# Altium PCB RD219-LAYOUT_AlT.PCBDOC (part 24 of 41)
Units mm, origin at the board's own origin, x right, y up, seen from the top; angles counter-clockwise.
Board outline 209.75 x 159.97 mm, 2 copper layers (TOP, BOTTOM), stack 0 mm thick; 398 components, 199 nets, 1469 pads, 0 vias.
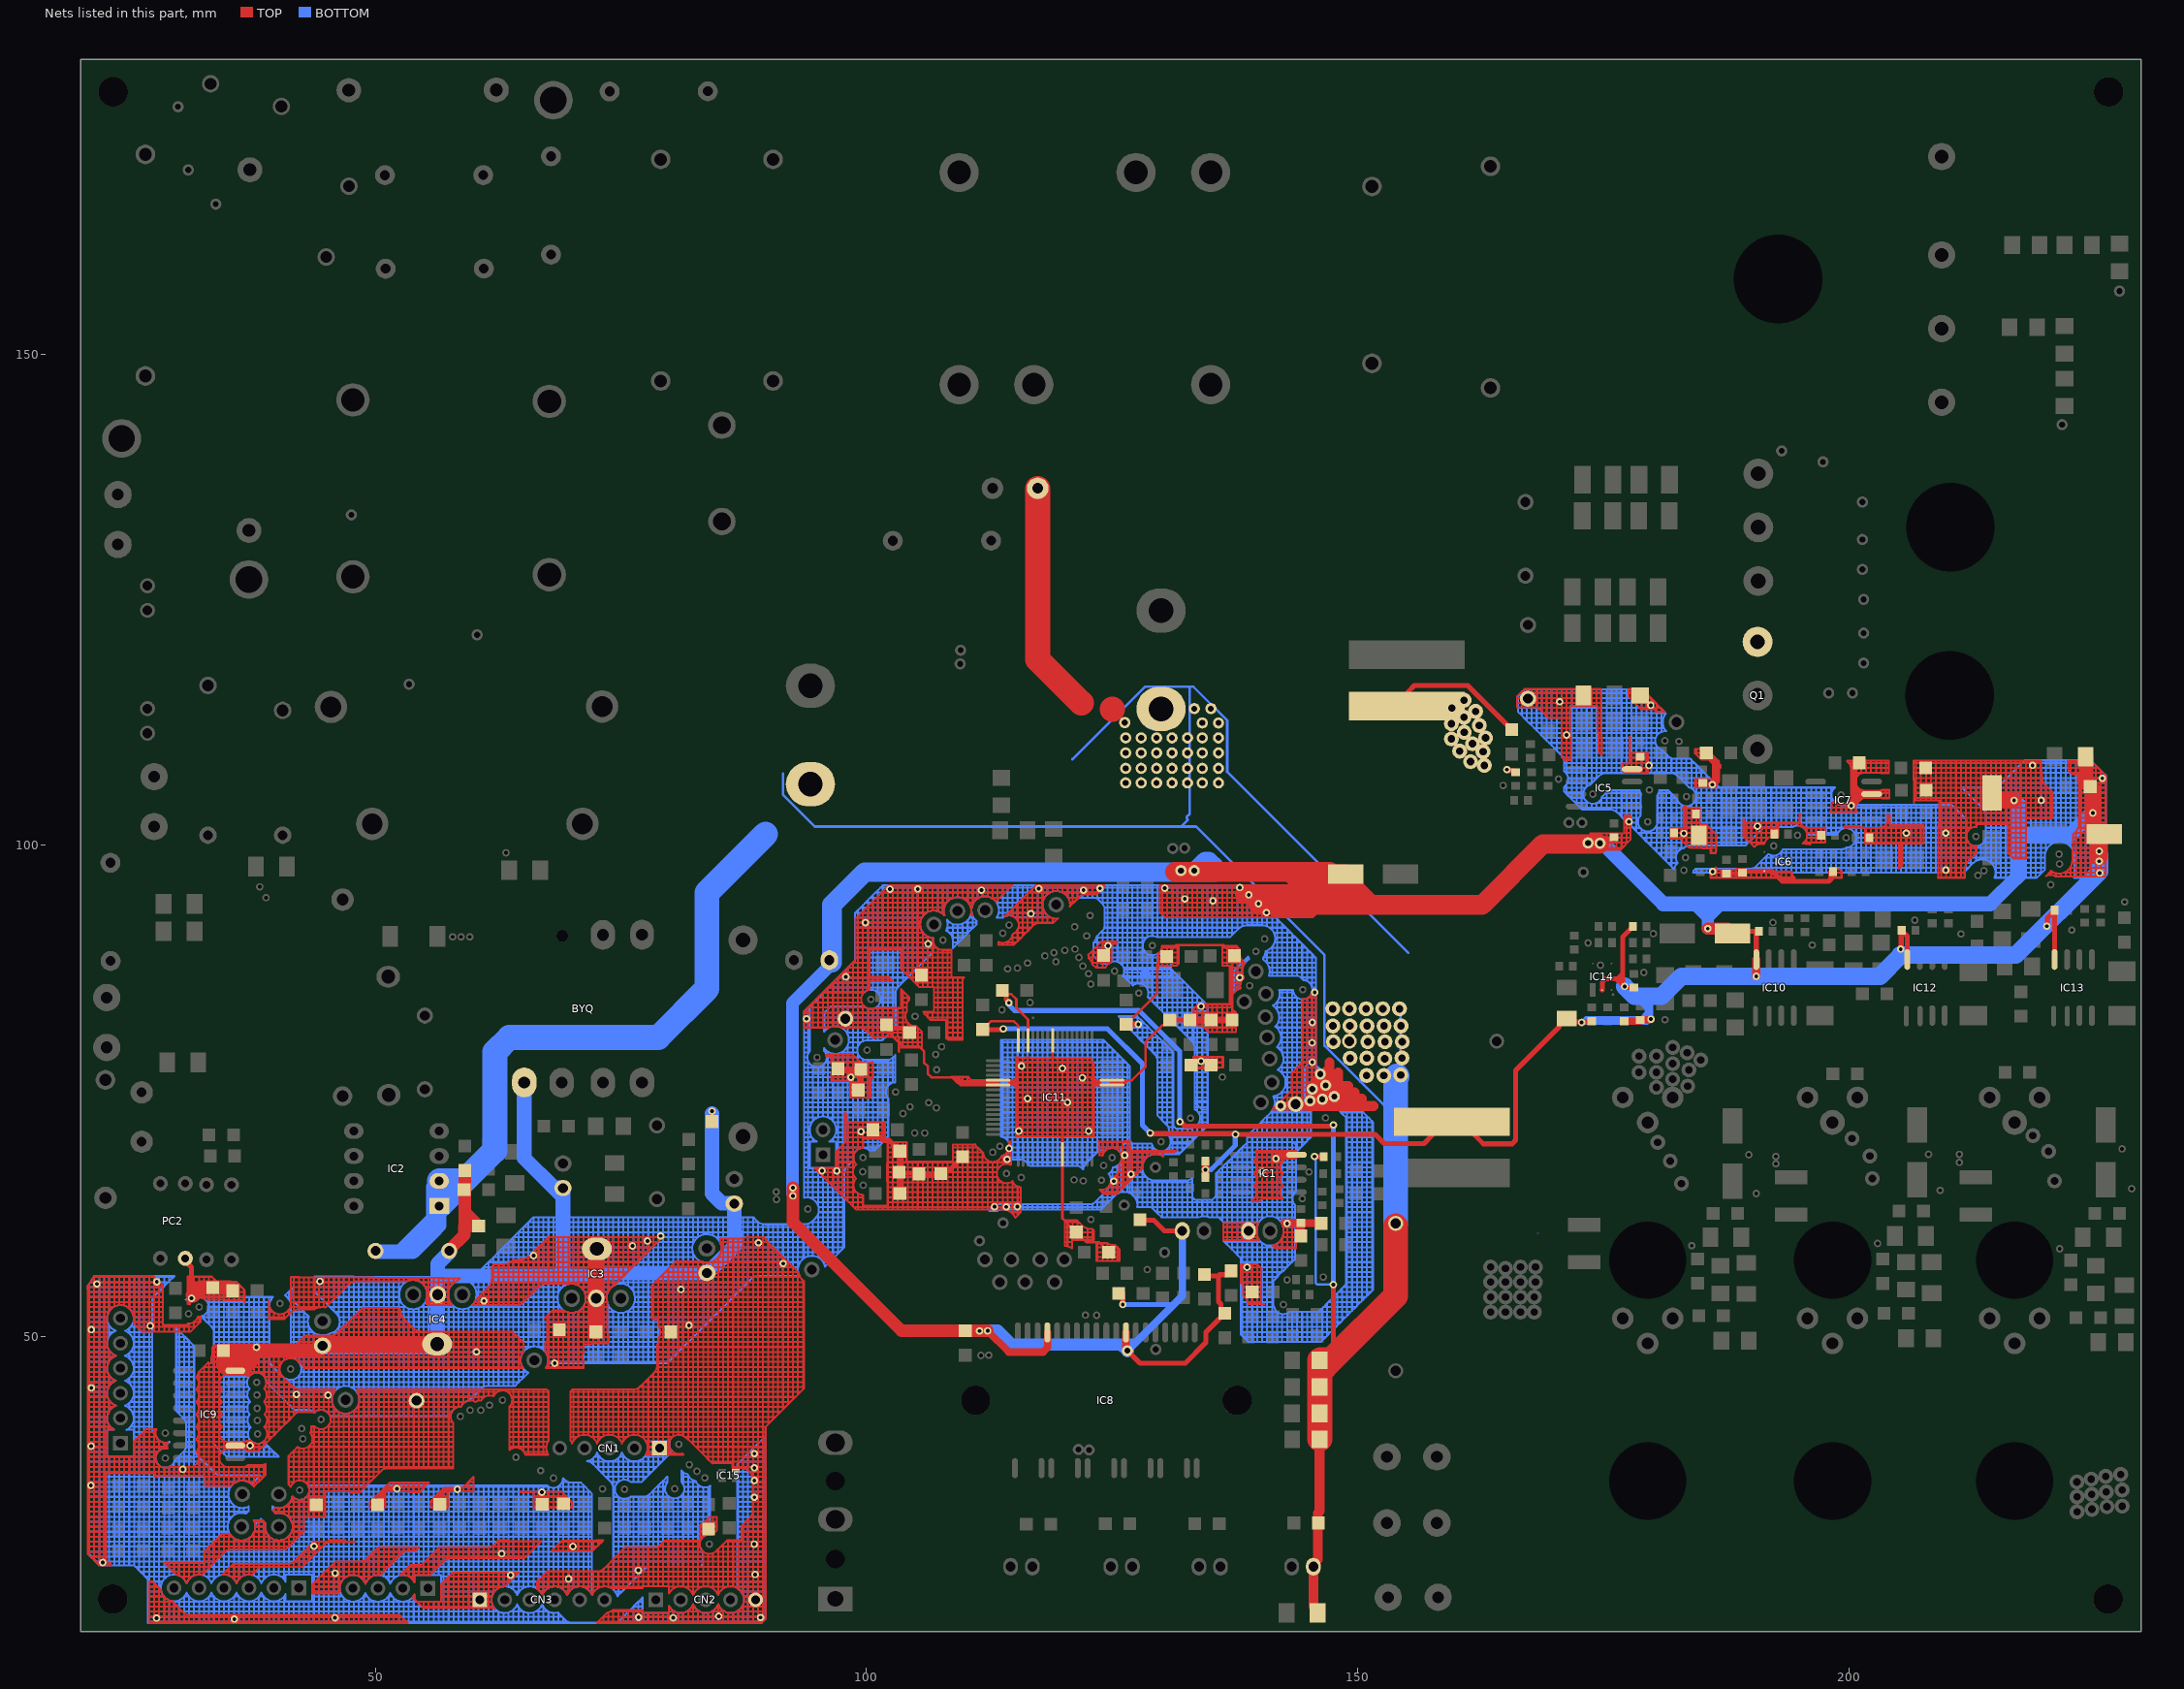
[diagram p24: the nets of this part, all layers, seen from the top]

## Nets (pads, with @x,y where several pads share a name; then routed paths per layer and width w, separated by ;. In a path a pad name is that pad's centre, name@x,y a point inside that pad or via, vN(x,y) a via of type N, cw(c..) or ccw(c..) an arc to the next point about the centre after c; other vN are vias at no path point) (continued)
GND: (continued)
  BOTTOM w0.203: 51.877,27.62 51.877,28.128 ; 51.877,27.62 52.385,27.62 ; 51.877,28.128 51.877,28.636 ; 51.877,28.128 52.385,28.128 ; 51.877,28.636 51.877,29.144 ; 51.877,28.636 52.385,28.636 ; 51.877,29.144 51.877,29.652 ; 51.877,29.144 52.385,29.144 ; 51.877,29.652 51.877,30.16 ; 51.877,29.652 52.385,29.652 ; 51.877,30.16 51.877,30.668 ; 51.877,30.16 52.385,30.16 ; 51.877,30.668 51.877,31.176 ; 51.877,30.668 52.385,30.668 ; 51.877,31.176 51.877,31.684 ; 51.877,31.176 52.385,31.176 ; 51.877,31.684 51.877,32.192 ; 51.877,31.684 52.385,31.684 ; 51.877,32.192 51.877,32.7 ; 51.877,32.192 52.385,32.192 ; 51.877,32.7 51.877,33.208 ; 51.877,32.7 52.385,32.7 ; 51.877,33.208 51.877,33.716 ; 51.877,33.208 52.385,33.208 ; 51.877,33.716 51.877,34.224 ; 51.877,33.716 52.385,33.716 ; 51.877,34.224 51.877,34.732 ; 51.877,34.224 pad.@52.385,34.224 ; 51.877,34.732 51.877,34.866 ; 51.877,34.732 pad.@52.385,34.732 ; 51.877,34.866 pad.@52.385,34.866 ; 51.877,41.938 51.877,42.352 ; 51.877,41.938 52.385,41.938 ; 51.877,42.352 51.877,42.86 ; 51.877,42.352 52.385,42.352 ; 51.877,42.86 51.877,43.368 ; 51.877,42.86 52.385,42.86 ; 51.877,43.368 51.877,43.876 ; 51.877,43.368 52.385,43.368 ; 51.877,43.876 51.877,44.384 ; 51.877,43.876 52.385,43.876 ; 51.877,44.384 51.877,44.892 ; 51.877,44.384 52.385,44.384 ; 51.877,44.892 51.877,45.4 ; 51.877,44.892 52.385,44.892 ; 51.877,45.4 51.877,45.908 ; 51.877,45.4 52.385,45.4 ; 51.877,45.908 51.877,46.416 ; 51.877,45.908 52.385,45.908 ; 51.877,46.416 51.877,46.924 ; 51.877,46.416 52.385,46.416 ; 51.877,46.924 51.877,47.432 ; 51.877,46.924 52.385,46.924 ; 51.877,47.432 51.877,47.94 ; 51.877,47.432 52.385,47.432 ; 51.877,47.94 51.877,48.448 ; 51.877,47.94 52.385,47.94 ; 51.877,48.448 51.877,48.956 ; 51.877,48.448 52.385,48.448 ; 51.877,48.956 51.877,49.464 ; 51.877,48.956 52.385,48.956 ; 51.877,49.464 51.877,49.972 ; 51.877,49.464 52.385,49.464 ; 51.877,49.972 51.877,50.48 ; 51.877,49.972 52.385,49.972 ; 51.877,50.48 51.877,50.988 ; 51.877,50.48 52.385,50.48 ; 51.877,50.988 51.877,51.496 ; 51.877,50.988 52.385,50.988 ; 51.877,51.496 51.877,52.004 ; 51.877,51.496 52.385,51.496 ; 51.877,52.004 51.877,52.512 ; 51.877,52.004 52.385,52.004 ; 51.877,52.512 51.877,53.02 ; 51.877,52.512 52.385,52.512 ; 51.877,53.02 51.877,53.528 ; 51.877,53.02 52.385,53.02 ; 51.877,53.528 51.877,54.036 ; 51.877,53.528 52.385,53.528 ; 51.877,54.036 52.385,54.036 ; 51.877,54.036 51.877,54.544 ; 51.877,54.544 51.877,55.052 ; 51.877,54.544 52.385,54.544 ; 51.877,55.052 51.877,55.56 ; 51.877,55.052 52.385,55.052 ; 51.877,55.56 51.877,56.068 ; 51.877,55.56 52.385,55.56 ; 51.877,56.068 51.877,56.095 ; 51.877,56.068 52.385,56.068 ; 51.877,56.095 52.385,56.093 ; 52.17,25.588 cw(c52.809,24.397) 52.174,25.59 cw(c52.809,24.397) 52.385,25.68 ; 52.385,20.889 52.385,21.016 ; 52.385,20.889 52.893,20.889 ; 52.385,21.016 52.385,21.524 ; 52.385,21.016 52.893,21.016 ; 52.385,21.524 52.385,22.032 ; 52.385,21.524 52.893,21.524 ; 52.385,22.032 52.385,22.54 ; 52.385,22.032 52.893,22.032 ; 52.385,22.54 52.385,23.048 ; 52.385,22.54 52.893,22.54 ; 52.385,23.048 52.725,23.048 ; 52.385,25.68 cw(c52.809,24.397) 52.391,25.682 cw(c52.809,24.397) 52.893,25.746 ; 52.385,25.68 52.385,26.096 ; 52.385,26.096 52.385,26.604 ; 52.385,26.096 52.893,26.096 ; 52.385,26.604 52.385,27.112 ; 52.385,26.604 52.893,26.604 ; 52.385,27.112 52.385,27.62 ; 52.385,27.112 52.893,27.112 ; 52.385,27.62 52.385,28.128 ; 52.385,27.62 52.893,27.62 ; 52.385,28.128 52.385,28.636 ; 52.385,28.128 52.893,28.128 ; 52.385,28.636 52.385,29.144 ; 52.385,28.636 52.893,28.636 ; 52.385,29.144 52.385,29.652 ; 52.385,29.144 52.893,29.144 ; 52.385,29.652 52.385,30.16 ; 52.385,29.652 52.893,29.652 ; 52.385,30.16 52.385,30.668 ; 52.385,30.16 52.893,30.16 ; 52.385,30.668 52.385,31.176 ; 52.385,30.668 52.893,30.668 ; 52.385,31.176 52.385,31.684 ; 52.385,31.176 52.893,31.176 ; 52.385,31.684 52.385,32.192 ; 52.385,31.684 52.893,31.684 ; 52.385,32.192 52.385,32.7 ; 52.385,32.192 52.893,32.192 ; 52.385,32.7 52.385,33.208 ; 52.385,32.7 52.893,32.7 ; 52.385,33.208 52.385,33.716 ; 52.385,33.208 52.893,33.208 ; 52.385,33.716 pad.@52.385,34.224 ; 52.385,33.716 52.893,33.716 ; pad.@52.385,34.224 52.893,34.224 ; pad.@52.385,34.224 pad.@52.385,34.732 ; pad.@52.385,34.732 pad.@52.385,34.866 ; pad.@52.385,34.732 52.893,34.732 ; pad.@52.385,34.866 52.893,34.866 ; 52.385,41.938 52.385,42.352 ; 52.385,41.938 52.893,41.938 ; 52.385,42.352 52.385,42.86 ; 52.385,42.352 52.893,42.352 ; 52.385,42.86 52.385,43.368 ; 52.385,42.86 52.893,42.86 ; 52.385,43.368 52.385,43.876 ; 52.385,43.368 52.893,43.368 ; 52.385,43.876 52.385,44.384 ; 52.385,43.876 52.893,43.876 ; 52.385,44.384 52.385,44.892 ; 52.385,44.384 52.893,44.384 ; 52.385,44.892 52.385,45.4 ; 52.385,44.892 52.893,44.892 ; 52.385,45.4 52.385,45.908 ; 52.385,45.4 52.893,45.4 ; 52.385,45.908 52.385,46.416 ; 52.385,45.908 52.893,45.908 ; 52.385,46.416 52.385,46.924 ; 52.385,46.416 52.893,46.416 ; 52.385,46.924 52.385,47.432 ; 52.385,46.924 52.893,46.924 ; 52.385,47.432 52.385,47.94 ; 52.385,47.432 52.893,47.432 ; 52.385,47.94 52.385,48.448 ; 52.385,47.94 52.893,47.94 ; 52.385,48.448 52.385,48.956 ; 52.385,48.448 52.893,48.448 ; 52.385,48.956 52.385,49.464 ; 52.385,48.956 52.893,48.956 ; 52.385,49.464 52.385,49.972 ; 52.385,49.464 52.893,49.464 ; 52.385,49.972 52.385,50.48 ; 52.385,49.972 52.893,49.972 ; 52.385,50.48 52.385,50.988 ; 52.385,50.48 52.893,50.48 ; 52.385,50.988 52.385,51.496 ; 52.385,50.988 52.893,50.988 ; 52.385,51.496 52.385,52.004 ; 52.385,51.496 52.893,51.496 ; 52.385,52.004 52.385,52.512 ; 52.385,52.004 52.893,52.004 ; 52.385,52.512 52.385,53.02 ; 52.385,52.512 52.893,52.512 ; 52.385,53.02 52.385,53.528 ; 52.385,53.02 52.893,53.02 ; 52.385,53.528 52.385,54.036 ; 52.385,53.528 52.618,53.528 ; 52.385,54.036 52.385,54.544 ; 52.385,54.036 52.448,54.036 ; 52.385,54.544 52.385,55.052 ; 52.385,54.544 52.448,54.544 ; 52.385,55.052 52.385,55.56 ; 52.385,55.052 52.618,55.052 ; 52.385,55.56 52.385,56.068 ; 52.385,55.56 52.893,55.56 ; 52.385,56.068 52.385,56.093 ; 52.385,56.068 52.893,56.068 ; 52.385,56.093 52.893,56.091 ; 52.448,54.036 ccw(c53.862,54.227) 52.614,53.535 ccw(c53.862,54.227) 52.618,53.528 ; 52.448,54.036 cw(c53.862,54.227) 52.435,54.227 52.435,54.354 cw(c53.862,54.354) 52.448,54.544 ; 52.448,54.544 cw(c53.862,54.354) 52.614,55.045 cw(c53.862,54.354) 52.618,55.052 ; 52.618,53.528 ccw(c53.862,54.227) 52.889,53.183 ccw(c53.862,54.227) 52.893,53.179 ; 52.893,20.889 52.893,21.016 ; 52.893,20.889 53.401,20.889 ; 52.893,21.016 52.893,21.524 ; 52.893,21.016 53.401,21.016 ; 52.893,21.524 52.893,22.032 ; 52.893,21.524 53.401,21.524 ; 52.893,22.032 52.893,22.54 ; 52.893,22.032 53.401,22.032 ; 52.893,22.54 53.401,22.54 ; 52.893,22.54 52.893,23.048 ; 52.893,23.048 ccw(c52.809,24.397) 53.401,23.182 ; 52.893,23.048 53.401,23.048 ; 52.893,25.746 cw(c52.809,24.397) 53.401,25.612 ; 52.893,25.746 52.893,26.096 ; 52.893,26.096 52.893,26.604 ; 52.893,26.096 53.401,26.096 ; 52.893,26.604 52.893,27.112 ; 52.893,26.604 53.401,26.604 ; 52.893,27.112 52.893,27.62 ; 52.893,27.112 53.401,27.112 ; 52.893,27.62 52.893,28.128 ; 52.893,27.62 53.401,27.62 ; 52.893,28.128 52.893,28.636 ; 52.893,28.128 53.401,28.128 ; 52.893,28.636 52.893,29.144 ; 52.893,28.636 53.401,28.636 ; 52.893,29.144 52.893,29.652 ; 52.893,29.144 53.401,29.144 ; 52.893,29.652 52.893,30.16 ; 52.893,29.652 53.401,29.652 ; 52.893,30.16 52.893,30.668 ; 52.893,30.16 53.401,30.16 ; 52.893,30.668 52.893,31.176 ; 52.893,30.668 53.401,30.668 ; 52.893,31.176 52.893,31.684 ; 52.893,31.176 53.401,31.176 ; 52.893,31.684 52.893,32.192 ; 52.893,31.684 53.401,31.684 ; 52.893,32.192 52.893,32.7 ; 52.893,32.192 53.401,32.192 ; 52.893,32.7 52.893,33.208 ; 52.893,32.7 53.401,32.7 ; 52.893,33.208 52.893,33.716 ; 52.893,33.208 53.401,33.208 ; 52.893,33.716 52.893,34.224 ; 52.893,33.716 53.401,33.716 ; 52.893,34.224 52.893,34.732 ; 52.893,34.224 53.401,34.224 ; 52.893,34.732 52.893,34.866 ; 52.893,34.732 53.401,34.732 ; 52.893,34.866 53.401,34.866 ; 52.893,41.938 52.893,42.352 ; 52.893,41.938 53.401,41.938 ; 52.893,42.352 52.893,42.86 ; 52.893,42.352 53.401,42.352 ; 52.893,42.86 52.893,43.368 ; 52.893,42.86 53.401,42.86 ; 52.893,43.368 52.893,43.876 ; 52.893,43.368 53.401,43.368 ; 52.893,43.876 52.893,44.384 ; 52.893,43.876 53.401,43.876 ; 52.893,44.384 52.893,44.892 ; 52.893,44.384 53.401,44.384 ; 52.893,44.892 52.893,45.4 ; 52.893,44.892 53.401,44.892 ; 52.893,45.4 52.893,45.908 ; 52.893,45.4 53.401,45.4 ; 52.893,45.908 52.893,46.416 ; 52.893,45.908 53.401,45.908 ; 52.893,46.416 52.893,46.924 ; 52.893,46.416 53.401,46.416 ; 52.893,46.924 52.893,47.432 ; 52.893,46.924 53.401,46.924 ; 52.893,47.432 52.893,47.94 ; 52.893,47.432 53.401,47.432 ; 52.893,47.94 52.893,48.448 ; 52.893,47.94 53.401,47.94 ; 52.893,48.448 52.893,48.956 ; 52.893,48.448 53.401,48.448 ; 52.893,48.956 52.893,49.464 ; 52.893,48.956 53.401,48.956 ; 52.893,49.464 52.893,49.972 ; 52.893,49.464 53.401,49.464 ; 52.893,49.972 52.893,50.48 ; 52.893,49.972 53.401,49.972 ; 52.893,50.48 52.893,50.988 ; 52.893,50.48 53.401,50.48 ; 52.893,50.988 52.893,51.496 ; 52.893,50.988 53.401,50.988 ; 52.893,51.496 52.893,52.004 ; 52.893,51.496 53.401,51.496 ; 52.893,52.004 52.893,52.512 ; 52.893,52.004 53.401,52.004 ; 52.893,52.512 52.893,53.02 ; 52.893,52.512 53.401,52.512 ; 52.893,53.02 52.893,53.179 ; 52.893,55.56 52.893,56.068 ; 52.893,55.56 53.1,55.56 ; 52.893,56.068 52.893,56.091 ; 52.893,56.068 53.401,56.068 ; 52.893,56.091 53.401,56.09 ; 53.1,55.56 cw(c53.862,54.354) 53.106,55.564 cw(c53.862,54.354) 53.397,55.703 cw(c53.862,54.354) 53.401,55.704 ; 53.401,20.889 53.401,21.016 ; 53.401,20.889 53.909,20.889 ; 53.401,21.016 53.401,21.524 ; 53.401,21.016 53.909,21.016 ; 53.401,21.524 53.401,22.032 ; 53.401,21.524 53.909,21.524 ; 53.401,22.032 53.401,22.54 ; 53.401,22.032 53.909,22.032 ; 53.401,22.54 53.401,23.048 ; 53.401,22.54 53.909,22.54 ; 53.401,23.048 53.909,23.048 ; 53.401,23.048 53.401,23.182 ; 53.401,23.182 ccw(c52.809,24.397) 53.867,23.556 ; 53.401,25.612 53.401,26.096 ; 53.401,26.096 53.401,26.604 ; 53.401,26.096 53.909,26.096 ; 53.401,26.604 53.401,27.112 ; 53.401,26.604 53.909,26.604 ; 53.401,27.112 53.401,27.62 ; 53.401,27.112 53.909,27.112 ; 53.401,27.62 53.401,28.128 ; 53.401,27.62 53.909,27.62 ; 53.401,28.128 53.401,28.636 ; 53.401,28.128 53.909,28.128 ; 53.401,28.636 53.401,29.144 ; 53.401,28.636 53.909,28.636 ; 53.401,29.144 53.401,29.652 ; 53.401,29.144 53.909,29.144 ; 53.401,29.652 53.401,30.16 ; 53.401,29.652 53.909,29.652 ; 53.401,30.16 53.401,30.668 ; 53.401,30.16 53.909,30.16 ; 53.401,30.668 53.401,31.176 ; 53.401,30.668 53.909,30.668 ; 53.401,31.176 53.401,31.684 ; 53.401,31.176 53.909,31.176 ; 53.401,31.684 53.401,32.192 ; 53.401,31.684 53.909,31.684 ; 53.401,32.192 53.401,32.7 ; 53.401,32.192 53.909,32.192 ; 53.401,32.7 53.401,33.208 ; 53.401,32.7 53.909,32.7 ; 53.401,33.208 53.401,33.716 ; 53.401,33.208 53.909,33.208 ; 53.401,33.716 53.401,34.224 ; 53.401,33.716 53.909,33.716 ; 53.401,34.224 53.401,34.732 ; 53.401,34.224 53.909,34.224 ; 53.401,34.732 53.401,34.866 ; 53.401,34.732 53.909,34.732 ; 53.401,34.866 53.909,34.866 ; 53.401,41.938 53.401,42.352 ; 53.401,41.938 53.909,41.938 ; 53.401,42.352 53.401,42.86 ; 53.401,42.352 53.909,42.352 ; 53.401,42.86 53.401,43.368 ; 53.401,42.86 TP30.1@53.909,42.86 ; 53.401,43.368 TP30.1@53.909,43.368 ; 53.401,43.368 53.401,43.876 ; 53.401,43.876 53.401,44.384 ; 53.401,43.876 TP30.1@53.909,43.876 ; 53.401,44.384 53.401,44.892 ; 53.401,44.384 53.909,44.384 ; 53.401,44.892 53.401,45.4 ; 53.401,44.892 53.909,44.892 ; 53.401,45.4 53.401,45.908 ; 53.401,45.4 53.909,45.4 ; 53.401,45.908 53.401,46.416 ; 53.401,45.908 53.909,45.908 ; 53.401,46.416 53.401,46.924 ; 53.401,46.416 53.909,46.416 ; 53.401,46.924 53.401,47.432 ; 53.401,46.924 53.909,46.924 ; 53.401,47.432 53.401,47.94 ; 53.401,47.432 53.909,47.432 ; 53.401,47.94 53.401,48.448 ; 53.401,47.94 53.909,47.94 ; 53.401,48.448 53.401,48.956 ; 53.401,48.448 53.909,48.448 ; 53.401,48.956 53.401,49.464 ; 53.401,48.956 53.909,48.956 ; 53.401,49.464 53.401,49.972 ; 53.401,49.464 53.909,49.464 ; 53.401,49.972 53.401,50.48 ; 53.401,49.972 53.909,49.972 ; 53.401,50.48 53.401,50.988 ; 53.401,50.48 53.909,50.48 ; 53.401,50.988 53.401,51.496 ; 53.401,50.988 53.909,50.988 ; 53.401,51.496 53.401,52.004 ; 53.401,51.496 53.909,51.496 ; 53.401,52.004 53.401,52.512 ; 53.401,52.004 53.909,52.004 ; 53.401,52.512 53.909,52.512 ; 53.401,52.512 53.401,52.876 ; 53.401,52.876 ccw(c53.862,54.227) 53.909,52.8 ; 53.401,55.704 cw(c53.862,54.354) 53.909,55.78 ; 53.401,55.704 53.401,56.068 ; 53.401,56.068 53.401,56.09 ; 53.401,56.068 53.909,56.068 ; 53.401,56.09 53.909,56.088 ; 53.867,23.556 ccw(c52.809,24.397) 53.909,23.612 ; 53.867,23.556 53.909,23.556 ; 53.909,20.889 53.909,21.016 ; 53.909,20.889 54.417,20.889 ; 53.909,21.016 53.909,21.524 ; 53.909,21.016 54.417,21.016 ; 53.909,21.524 53.909,22.032 ; 53.909,21.524 54.417,21.524 ; 53.909,22.032 53.909,22.54 ; 53.909,22.032 54.417,22.032 ; 53.909,22.54 53.909,23.048 ; 53.909,22.54 54.417,22.54 ; 53.909,23.048 53.997,23.048 ; 53.909,23.048 53.909,23.556 ; 53.909,23.556 53.997,23.556 ; 53.909,23.556 53.909,23.612 ; 53.909,23.612 ccw(c52.809,24.397) 53.997,23.753 ; 53.909,25.182 cw(c52.809,24.397) 53.997,25.041 ; 53.909,25.182 53.909,25.588 ; 53.909,25.588 53.909,26.096 ; 53.909,25.588 53.997,25.588 ; 53.909,26.096 53.909,26.604 ; 53.909,26.096 54.417,26.096 ; 53.909,26.604 53.909,27.112 ; 53.909,26.604 54.417,26.604 ; 53.909,27.112 53.909,27.62 ; 53.909,27.112 54.417,27.112 ; 53.909,27.62 53.909,28.128 ; 53.909,27.62 54.417,27.62 ; 53.909,28.128 53.909,28.636 ; 53.909,28.128 54.417,28.128 ; 53.909,28.636 53.909,29.144 ; 53.909,28.636 54.417,28.636 ; 53.909,29.144 53.909,29.652 ; 53.909,29.144 54.417,29.144 ; 53.909,29.652 53.909,30.16 ; 53.909,29.652 54.417,29.652 ; 53.909,30.16 53.909,30.668 ; 53.909,30.16 54.417,30.16 ; 53.909,30.668 53.909,31.176 ; 53.909,30.668 54.417,30.668 ; 53.909,31.176 53.909,31.684 ; 53.909,31.176 54.417,31.176 ; 53.909,31.684 53.909,32.192 ; 53.909,31.684 54.417,31.684 ; 53.909,32.192 53.909,32.7 ; 53.909,32.192 54.417,32.192 ; 53.909,32.7 53.909,33.208 ; 53.909,32.7 54.417,32.7 ; 53.909,33.208 53.909,33.716 ; 53.909,33.208 54.417,33.208 ; 53.909,33.716 53.909,34.224 ; 53.909,33.716 54.417,33.716 ; 53.909,34.224 53.909,34.732 ; 53.909,34.224 54.417,34.224 ; 53.909,34.732 53.909,34.866 ; 53.909,34.732 54.417,34.732 ; 53.909,34.866 54.417,34.866 ; 53.909,41.938 53.909,42.352 ; 53.909,41.938 54.417,41.938 ; 53.909,42.352 TP30.1@53.909,42.86 ; 53.909,42.352 54.417,42.352 ; TP30.1@53.909,42.86 TP30.1@53.909,43.368 ; TP30.1@53.909,42.86 TP30.1@54.417,42.86 ; TP30.1@53.909,43.368 TP30.1@54.417,43.368 ; TP30.1@53.909,43.368 TP30.1@53.909,43.876 ; TP30.1@53.909,43.876 53.909,44.384 ; TP30.1@53.909,43.876 TP30.1@54.417,43.876 ; 53.909,44.384 53.909,44.892 ; 53.909,44.384 54.417,44.384 ; 53.909,44.892 53.909,45.4 ; 53.909,44.892 54.417,44.892 ; 53.909,45.4 53.909,45.908 ; 53.909,45.4 54.417,45.4 ; 53.909,45.908 53.909,46.416 ; 53.909,45.908 54.417,45.908 ; 53.909,46.416 53.909,46.924 ; 53.909,46.416 54.417,46.416 ; 53.909,46.924 53.909,47.432 ; 53.909,46.924 54.417,46.924 ; 53.909,47.432 53.909,47.94 ; 53.909,47.432 54.417,47.432 ; 53.909,47.94 53.909,48.448 ; 53.909,47.94 54.417,47.94 ; 53.909,48.448 53.909,48.956 ; 53.909,48.448 54.417,48.448 ; 53.909,48.956 53.909,49.464 ; 53.909,48.956 54.417,48.956 ; 53.909,49.464 53.909,49.972 ; 53.909,49.464 54.417,49.464 ; 53.909,49.972 53.909,50.48 ; 53.909,49.972 54.417,49.972 ; 53.909,50.48 53.909,50.988 ; 53.909,50.48 54.417,50.48 ; 53.909,50.988 53.909,51.496 ; 53.909,50.988 54.417,50.988 ; 53.909,51.496 53.909,52.004 ; 53.909,51.496 54.417,51.496 ; 53.909,52.004 53.909,52.512 ; 53.909,52.004 54.417,52.004 ; 53.909,52.512 54.417,52.512 ; 53.909,52.512 53.909,52.8 ; 53.909,52.8 ccw(c53.862,54.227) 53.912,52.8 ccw(c53.862,54.227) 54.417,52.912 ; 53.909,55.78 cw(c53.862,54.354) 53.912,55.78 cw(c53.862,54.354) 54.417,55.668 ; 53.909,55.78 53.909,56.068 ; 53.909,56.068 53.909,56.088 ; 53.909,56.068 54.417,56.068 ; 53.909,56.088 54.417,56.086 ; 53.997,23.048 53.997,23.556 ; 53.997,23.048 53.997,23.045 54.417,23.045 ; 53.997,23.556 53.997,23.753 ; 53.997,25.041 53.997,25.588 ; 53.997,25.588 53.997,25.749 54.417,25.749 ; 54.417,20.889 54.417,21.016 ; 54.417,20.889 54.925,20.889 ; 54.417,21.016 54.417,21.524 ; 54.417,21.016 54.925,21.016 ; 54.417,21.524 54.417,22.032 ; 54.417,21.524 54.925,21.524 ; 54.417,22.032 54.417,22.54 ; 54.417,22.032 54.925,22.032 ; 54.417,22.54 54.417,23.045 ; 54.417,22.54 54.925,22.54 ; 54.417,23.045 54.925,23.045 ; 54.417,25.749 54.417,26.096 ; 54.417,25.749 54.925,25.749 ; 54.417,26.096 54.417,26.604 ; 54.417,26.096 54.925,26.096 ; 54.417,26.604 54.417,27.112 ; 54.417,26.604 54.925,26.604 ; 54.417,27.112 54.417,27.62 ; 54.417,27.112 54.925,27.112 ; 54.417,27.62 54.417,28.128 ; 54.417,27.62 54.925,27.62 ; 54.417,28.128 54.417,28.636 ; 54.417,28.128 54.925,28.128 ; 54.417,28.636 54.417,29.144 ; 54.417,28.636 54.925,28.636 ; 54.417,29.144 54.417,29.652 ; 54.417,29.144 54.925,29.144 ; 54.417,29.652 54.417,30.16 ; 54.417,29.652 54.925,29.652 ; 54.417,30.16 54.417,30.668 ; 54.417,30.16 54.925,30.16 ; 54.417,30.668 54.417,31.176 ; 54.417,30.668 54.925,30.668 ; 54.417,31.176 54.417,31.684 ; 54.417,31.176 54.925,31.176 ; 54.417,31.684 54.417,32.192 ; 54.417,31.684 54.925,31.684 ; 54.417,32.192 54.417,32.7 ; 54.417,32.192 54.925,32.192 ; 54.417,32.7 54.417,33.208 ; 54.417,32.7 54.925,32.7 ; 54.417,33.208 54.417,33.716 ; 54.417,33.208 54.925,33.208 ; 54.417,33.716 54.417,34.224 ; 54.417,33.716 54.925,33.716 ; 54.417,34.224 54.417,34.732 ; 54.417,34.224 54.925,34.224 ; 54.417,34.732 54.417,34.866 ; 54.417,34.732 54.925,34.732 ; 54.417,34.866 54.925,34.866 ; 54.417,41.938 54.417,42.352 ; 54.417,41.938 54.925,41.938 ; 54.417,42.352 TP30.1@54.417,42.86 ; 54.417,42.352 54.925,42.352 ; TP30.1@54.417,42.86 TP30.1@54.417,43.368 ; TP30.1@54.417,42.86 54.925,42.86 ; TP30.1@54.417,43.368 TP30.1@54.925,43.368 ; TP30.1@54.417,43.368 TP30.1@54.417,43.876 ; TP30.1@54.417,43.876 54.417,44.384 ; TP30.1@54.417,43.876 54.925,43.876 ; 54.417,44.384 54.417,44.892 ; 54.417,44.384 54.925,44.384 ; 54.417,44.892 54.417,45.4 ; 54.417,44.892 54.925,44.892 ; 54.417,45.4 54.417,45.908 ; 54.417,45.4 54.925,45.4 ; 54.417,45.908 54.417,46.416 ; 54.417,45.908 54.925,45.908 ; 54.417,46.416 54.417,46.924 ; 54.417,46.416 54.925,46.416 ; 54.417,46.924 54.417,47.432 ; 54.417,46.924 54.925,46.924 ; 54.417,47.432 54.417,47.94 ; 54.417,47.432 54.925,47.432 ; 54.417,47.94 54.417,48.448 ; 54.417,47.94 54.925,47.94 ; 54.417,48.448 54.417,48.956 ; 54.417,48.448 54.925,48.448 ; 54.417,48.956 54.417,49.464 ; 54.417,48.956 IC4.4@54.925,48.956 ; 54.417,49.464 54.417,49.972 ; 54.417,49.464 IC4.4@54.925,49.464 ; 54.417,49.972 54.417,50.48 ; 54.417,49.972 54.925,49.972 ; 54.417,50.48 54.417,50.988 ; 54.417,50.48 54.925,50.48 ; 54.417,50.988 54.417,51.496 ; 54.417,50.988 54.925,50.988 ; 54.417,51.496 54.417,52.004 ; 54.417,51.496 54.925,51.496 ; 54.417,52.004 54.417,52.512 ; 54.417,52.004 54.925,52.004 ; 54.417,52.512 54.925,52.512 ; 54.417,52.512 54.417,52.912 ; 54.417,52.912 ccw(c53.862,54.227) 54.42,52.913 ccw(c53.862,54.227) 54.618,53.016 ccw(c53.862,54.227) 54.624,53.02 ; 54.417,55.668 cw(c53.862,54.354) 54.42,55.667 cw(c53.862,54.354) 54.618,55.564 cw(c53.862,54.354) 54.624,55.56 ; 54.417,55.668 54.417,56.068 ; 54.417,56.068 54.417,56.086 ; 54.417,56.068 54.925,56.068 ; 54.417,56.086 54.925,56.085 ; 54.624,53.02 ccw(c53.862,54.227) 54.923,53.272 ccw(c53.862,54.227) 54.925,53.274 ; 54.624,53.02 54.925,53.02 ; 54.624,55.56 cw(c53.862,54.354) 54.923,55.308 cw(c53.862,54.354) 54.925,55.306 ; 54.624,55.56 54.925,55.56 ; 54.925,20.889 54.925,21.016 ; 54.925,20.889 55.433,20.889 ; 54.925,21.016 54.925,21.524 ; 54.925,21.016 55.433,21.016 ; 54.925,21.524 54.925,22.032 ; 54.925,21.524 55.433,21.524 ; 54.925,22.032 54.925,22.54 ; 54.925,22.032 55.433,22.032 ; 54.925,22.54 54.925,23.045 ; 54.925,22.54 55.433,22.54 ; 54.925,23.045 55.433,23.045 ; 54.925,25.749 54.925,26.096 ; 54.925,25.749 55.433,25.749 ; 54.925,26.096 54.925,26.604 ; 54.925,26.096 55.433,26.096 ; 54.925,26.604 54.925,27.112 ; 54.925,26.604 55.433,26.604 ; 54.925,27.112 54.925,27.62 ; 54.925,27.112 55.433,27.112 ; 54.925,27.62 54.925,28.128 ; 54.925,27.62 55.433,27.62 ; 54.925,28.128 54.925,28.636 ; 54.925,28.128 55.433,28.128 ; 54.925,28.636 54.925,29.144 ; 54.925,28.636 55.433,28.636 ; 54.925,29.144 54.925,29.652 ; 54.925,29.144 55.433,29.144 ; 54.925,29.652 54.925,30.16 ; 54.925,29.652 55.433,29.652 ; 54.925,30.16 54.925,30.668 ; 54.925,30.16 55.433,30.16 ; 54.925,30.668 54.925,31.176 ; 54.925,30.668 55.433,30.668 ; 54.925,31.176 54.925,31.684 ; 54.925,31.176 55.433,31.176 ; 54.925,31.684 54.925,32.192 ; 54.925,31.684 55.433,31.684 ; 54.925,32.192 54.925,32.7 ; 54.925,32.192 55.433,32.192 ; 54.925,32.7 54.925,33.208 ; 54.925,32.7 55.433,32.7 ; 54.925,33.208 54.925,33.716 ; 54.925,33.208 55.433,33.208 ; 54.925,33.716 54.925,34.224 ; 54.925,33.716 55.433,33.716 ; 54.925,34.224 54.925,34.732 ; 54.925,34.224 55.433,34.224 ; 54.925,34.732 54.925,34.866 ; 54.925,34.732 55.433,34.732 ; 54.925,34.866 55.433,34.866 ; 54.925,41.938 54.925,42.352 ; 54.925,41.938 55.433,41.938 ; 54.925,42.352 54.925,42.86 ; 54.925,42.352 55.433,42.352 ; 54.925,42.86 TP30.1@54.925,43.368 ; 54.925,42.86 55.433,42.86 ; TP30.1@54.925,43.368 55.433,43.368 ; TP30.1@54.925,43.368 54.925,43.876 ; 54.925,43.876 54.925,44.384 ; 54.925,43.876 55.433,43.876 ; 54.925,44.384 54.925,44.892 ; 54.925,44.384 55.433,44.384 ; 54.925,44.892 54.925,45.4 ; 54.925,44.892 55.433,44.892 ; 54.925,45.4 54.925,45.908 ; 54.925,45.4 55.433,45.4 ; 54.925,45.908 54.925,46.416 ; 54.925,45.908 55.433,45.908 ; 54.925,46.416 54.925,46.924 ; 54.925,46.416 55.433,46.416 ; 54.925,46.924 54.925,47.432 ; 54.925,46.924 55.433,46.924 ; 54.925,47.432 54.925,47.94 ; 54.925,47.432 55.433,47.432 ; 54.925,47.94 54.925,48.448 ; 54.925,47.94 55.433,47.94 ; 54.925,48.448 IC4.4@54.925,48.956 ; 54.925,48.448 IC4.4@55.433,48.448 ; IC4.4@54.925,48.956 55.402,48.956 IC4.4@55.433,48.956 ; IC4.4@54.925,48.956 IC4.4@54.925,49.464 ; IC4.4@54.925,49.464 54.925,49.972 ; IC4.4@54.925,49.464 IC4.4@55.433,49.464 ; 54.925,49.972 54.925,50.48 ; 54.925,49.972 IC4.4@55.433,49.972 ; 54.925,50.48 54.925,50.988 ; 54.925,50.48 55.433,50.48 ; 54.925,50.988 54.925,51.496 ; 54.925,50.988 55.433,50.988 ; 54.925,51.496 54.925,52.004 ; 54.925,51.496 55.433,51.496 ; 54.925,52.004 54.925,52.512 ; 54.925,52.004 55.433,52.004 ; 54.925,52.512 54.925,53.02 ; 54.925,52.512 55.433,52.512 ; 54.925,53.02 55.433,53.02 ; 54.925,53.02 54.925,53.274 ; 54.925,53.274 ccw(c53.862,54.227) 55.107,53.528 ; 54.925,55.306 cw(c53.862,54.354) 55.107,55.052 ; 54.925,55.306 54.925,55.56 ; 54.925,55.56 54.925,56.068 ; 54.925,55.56 55.433,55.56 ; 54.925,56.068 54.925,56.085 ; 54.925,56.068 55.433,56.068 ; 54.925,56.085 55.433,56.083 ; 55.107,53.528 ccw(c53.862,54.227) 55.11,53.535 ccw(c53.862,54.227) 55.276,54.036 ; 55.107,53.528 55.433,53.528 ; 55.107,55.052 cw(c53.862,54.354) 55.11,55.045 cw(c53.862,54.354) 55.276,54.544 ; 55.107,55.052 55.433,55.052 ; 55.276,54.036 ccw(c53.862,54.227) 55.289,54.227 55.289,54.354 ccw(c53.862,54.354) 55.276,54.544 ; 55.276,54.036 55.433,54.036 ; 55.276,54.544 55.433,54.544 ; 55.433,20.889 55.433,21.016 ; 55.433,20.889 55.941,20.889 ; 55.433,21.016 55.433,21.524 ; 55.433,21.016 55.941,21.016 ; 55.433,21.524 55.433,22.032 ; 55.433,21.524 55.941,21.524 ; 55.433,22.032 55.433,22.54 ; 55.433,22.032 55.941,22.032 ; 55.433,22.54 55.433,23.045 ; 55.433,22.54 55.941,22.54 ; 55.433,23.045 55.941,23.045 ; 55.433,25.749 55.433,26.096 ; 55.433,25.749 55.941,25.749 ; 55.433,26.096 55.433,26.604 ; 55.433,26.096 55.941,26.096 ; 55.433,26.604 55.433,27.112 ; 55.433,26.604 55.941,26.604 ; 55.433,27.112 55.433,27.62 ; 55.433,27.112 55.941,27.112 ; 55.433,27.62 55.433,28.128 ; 55.433,27.62 55.941,27.62 ; 55.433,28.128 55.433,28.636 ; 55.433,28.128 55.941,28.128 ; 55.433,28.636 55.433,29.144 ; 55.433,28.636 55.941,28.636 ; 55.433,29.144 55.433,29.652 ; 55.433,29.144 55.941,29.144 ; 55.433,29.652 55.433,30.16 ; 55.433,29.652 55.941,29.652 ; 55.433,30.16 55.433,30.668 ; 55.433,30.16 55.941,30.16 ; 55.433,30.668 55.433,31.176 ; 55.433,30.668 55.941,30.668 ; 55.433,31.176 55.433,31.684 ; 55.433,31.176 55.941,31.176 ; 55.433,31.684 55.433,32.192 ; 55.433,31.684 55.941,31.684 ; 55.433,32.192 55.433,32.7 ; 55.433,32.192 55.941,32.192 ; 55.433,32.7 55.433,33.208 ; 55.433,32.7 55.941,32.7 ; 55.433,33.208 55.433,33.716 ; 55.433,33.208 55.941,33.208 ; 55.433,33.716 55.433,34.224 ; 55.433,33.716 55.941,33.716 ; 55.433,34.224 55.433,34.732 ; 55.433,34.224 55.941,34.224 ; 55.433,34.732 55.433,34.866 ; 55.433,34.732 55.941,34.732 ; 55.433,34.866 55.941,34.866 ; 55.433,41.938 55.433,42.352 ; 55.433,41.938 55.941,41.938 ; 55.433,42.352 55.433,42.86 ; 55.433,42.352 55.941,42.352 ; 55.433,42.86 55.433,43.368 ; 55.433,42.86 55.941,42.86 ; 55.433,43.368 55.433,43.876 ; 55.433,43.368 55.941,43.368 ; 55.433,43.876 55.433,44.384 ; 55.433,43.876 55.941,43.876 ; 55.433,44.384 55.433,44.892 ; 55.433,44.384 55.941,44.384 ; 55.433,44.892 55.433,45.4 ; 55.433,44.892 55.941,44.892 ; 55.433,45.4 55.433,45.908 ; 55.433,45.4 55.941,45.4 ; 55.433,45.908 55.433,46.416 ; 55.433,45.908 55.941,45.908 ; 55.433,46.416 55.433,46.924 ; 55.433,46.416 55.941,46.416 ; 55.433,46.924 55.433,47.432 ; 55.433,46.924 55.941,46.924 ; 55.433,47.432 55.433,47.94 ; 55.433,47.432 55.941,47.432 ; 55.433,47.94 IC4.4@55.433,48.448 ; 55.433,47.94 55.941,47.94 ; IC4.4@55.433,48.448 IC4.4@55.433,48.956 ; IC4.4@55.433,48.448 IC4.4@55.941,48.448 ; IC4.4@55.433,48.956 55.433,48.987 IC4.4@55.433,49.464 ; IC4.4@55.433,48.956 IC4.4@55.941,48.956 ; IC4.4@55.433,49.464 IC4.4@55.433,49.972 ; IC4.4@55.433,49.464 IC4.4@55.941,49.464 ; IC4.4@55.433,49.972 55.433,50.48 ; IC4.4@55.433,49.972 IC4.4@55.941,49.972 ; 55.433,50.48 55.433,50.988 ; 55.433,50.48 55.941,50.48 ; 55.433,50.988 55.433,51.496 ; 55.433,50.988 55.941,50.988 ; 55.433,51.496 55.433,52.004 ; 55.433,51.496 55.941,51.496 ; 55.433,52.004 55.433,52.512 ; 55.433,52.004 55.941,52.004 ; 55.433,52.512 55.433,53.02 ; 55.433,52.512 55.941,52.512 ; 55.433,53.02 55.433,53.528 ; 55.433,53.02 55.941,53.02 ; 55.433,53.528 55.433,54.036 ; 55.433,53.528 IC4.2@55.941,53.528 ; 55.433,54.036 55.433,54.544 ; 55.433,54.036 IC4.2@55.941,54.036 ; 55.433,54.544 55.433,55.052 ; 55.433,54.544 IC4.2@55.941,54.544 ; 55.433,55.052 55.433,55.56 ; 55.433,55.052 IC4.2@55.941,55.052 ; 55.433,55.56 55.433,56.068 ; 55.433,55.56 55.941,55.56 ; 55.433,56.068 55.433,56.083 ; 55.433,56.068 55.941,56.068 ; 55.433,56.083 55.941,56.081 ; 55.941,20.889 55.941,21.016 ; 55.941,20.889 56.449,20.889 ; 55.941,21.016 55.941,21.524 ; 55.941,21.016 56.449,21.016 ; 55.941,21.524 55.941,22.032 ; 55.941,21.524 56.449,21.524 ; 55.941,22.032 55.941,22.54 ; 55.941,22.032 56.449,22.032 ; 55.941,22.54 55.941,23.045 ; 55.941,22.54 56.449,22.54 ; 55.941,23.045 56.449,23.045 ; 55.941,25.749 55.941,26.096 ; 55.941,25.749 56.449,25.749 ; 55.941,26.096 55.941,26.604 ; 55.941,26.096 56.449,26.096 ; 55.941,26.604 55.941,27.112 ; 55.941,26.604 56.449,26.604 ; 55.941,27.112 55.941,27.62 ; 55.941,27.112 56.449,27.112 ; 55.941,27.62 55.941,28.128 ; 55.941,27.62 56.449,27.62 ; 55.941,28.128 55.941,28.636 ; 55.941,28.128 56.449,28.128 ; 55.941,28.636 55.941,29.144 ; 55.941,28.636 56.449,28.636 ; 55.941,29.144 55.941,29.652 ; 55.941,29.144 56.449,29.144 ; 55.941,29.652 55.941,30.16 ; 55.941,29.652 56.449,29.652 ; 55.941,30.16 55.941,30.668 ; 55.941,30.16 56.449,30.16 ; 55.941,30.668 55.941,31.176 ; 55.941,30.668 56.449,30.668 ; 55.941,31.176 55.941,31.684 ; 55.941,31.176 56.449,31.176 ; 55.941,31.684 55.941,32.192 ; 55.941,31.684 56.449,31.684 ; 55.941,32.192 55.941,32.7 ; 55.941,32.192 56.449,32.192 ; 55.941,32.7 55.941,33.208 ; 55.941,32.7 56.449,32.7 ; 55.941,33.208 55.941,33.716 ; 55.941,33.208 56.449,33.208 ; 55.941,33.716 55.941,34.224 ; 55.941,33.716 56.449,33.716 ; 55.941,34.224 55.941,34.732 ; 55.941,34.224 56.449,34.224 ; 55.941,34.732 55.941,34.866 ; 55.941,34.732 56.449,34.732 ; 55.941,34.866 56.449,34.866 ; 55.941,41.938 55.941,42.352 ; 55.941,41.938 56.449,41.938 ; 55.941,42.352 55.941,42.86 ; 55.941,42.352 56.449,42.352 ; 55.941,42.86 55.941,43.368 ; 55.941,42.86 56.449,42.86 ; 55.941,43.368 55.941,43.876 ; 55.941,43.368 56.449,43.368 ; 55.941,43.876 55.941,44.384 ; 55.941,43.876 56.449,43.876 ; 55.941,44.384 55.941,44.892 ; 55.941,44.384 56.449,44.384 ; 55.941,44.892 55.941,45.4 ; 55.941,44.892 56.449,44.892 ; 55.941,45.4 55.941,45.908 ; 55.941,45.4 56.449,45.4 ; 55.941,45.908 55.941,46.416 ; 55.941,45.908 56.449,45.908 ; 55.941,46.416 55.941,46.924 ; 55.941,46.416 56.449,46.416 ; 55.941,46.924 55.941,47.432 ; 55.941,46.924 56.449,46.924 ; 55.941,47.432 55.941,47.94 ; 55.941,47.432 56.449,47.432 ; 55.941,47.94 IC4.4@55.941,48.448 ; 55.941,47.94 56.449,47.94 ; IC4.4@55.941,48.448 IC4.4@55.941,48.956 ; IC4.4@55.941,48.448 IC4.4@56.449,48.448 ; IC4.4@55.941,48.956 IC4.4@56.449,48.956 ; IC4.4@55.941,48.956 55.941,49.261 IC4.4@55.941,49.464 ; IC4.4@55.941,49.464 IC4.4@55.941,49.972 ; IC4.4@55.941,49.464 56.333,49.464 IC4.4@56.449,49.464 ; IC4.4@55.941,49.972 55.941,50.48 ; IC4.4@55.941,49.972 56.333,49.972 IC4.4@56.449,49.972 ; 55.941,50.48 55.941,50.988 ; 55.941,50.48 56.333,50.48 56.449,50.48 ; 55.941,50.988 56.333,50.988 56.449,50.988 ; 55.941,50.988 55.941,51.496 ; 55.941,51.496 55.941,52.004 ; 55.941,51.496 56.333,51.496 56.449,51.496 ; 55.941,52.004 56.333,52.004 56.449,52.004 ; 55.941,52.004 55.941,52.512 ; 55.941,52.512 55.941,53.02 ; 55.941,52.512 56.333,52.512 56.449,52.512 ; 55.941,53.02 56.333,53.02 56.449,53.02 ; 55.941,53.02 IC4.2@55.941,53.528 ; IC4.2@55.941,53.528 56.333,53.528 IC4.2@56.449,53.528 ; IC4.2@55.941,53.528 IC4.2@55.941,54.036 ; IC4.2@55.941,54.036 56.333,54.036 IC4.2@56.449,54.036 ; IC4.2@55.941,54.036 IC4.2@55.941,54.544 ; IC4.2@55.941,54.544 IC4.2@55.941,55.052 ; IC4.2@55.941,54.544 56.362,54.544 IC4.2@56.449,54.544 ; IC4.2@55.941,55.052 55.941,55.56 ; IC4.2@55.941,55.052 56.362,55.052 IC4.2@56.449,55.052 ; 55.941,55.56 56.362,55.56 56.449,55.56 ; 55.941,55.56 55.941,56.068 ; 55.941,56.068 55.941,56.081 ; 55.941,56.068 56.362,56.068 56.449,56.068 ; 55.941,56.081 56.362,56.08 56.374,56.08 56.449,56.08 ; 56.449,20.889 56.449,21.016 ; 56.449,20.889 56.957,20.889 ; 56.449,21.016 56.449,21.524 ; 56.449,21.016 56.957,21.016 ; 56.449,21.524 56.449,22.032 ; 56.449,21.524 56.957,21.524 ; 56.449,22.032 56.449,22.54 ; 56.449,22.032 56.957,22.032 ; 56.449,22.54 56.449,23.045 ; 56.449,22.54 56.957,22.54 ; 56.449,23.045 56.7,23.045 56.7,23.048 ; 56.449,25.749 56.449,26.096 ; 56.449,25.749 56.7,25.749 56.7,25.588 ; 56.449,26.096 56.449,26.604 ; 56.449,26.096 56.957,26.096 ; 56.449,26.604 56.449,27.112 ; 56.449,26.604 56.957,26.604 ; 56.449,27.112 56.449,27.62 ; 56.449,27.112 56.957,27.112 ; 56.449,27.62 56.449,28.128 ; 56.449,27.62 56.957,27.62 ; 56.449,28.128 56.449,28.636 ; 56.449,28.128 56.957,28.128 ; 56.449,28.636 56.449,29.144 ; 56.449,28.636 56.957,28.636 ; 56.449,29.144 56.449,29.652 ; 56.449,29.144 56.957,29.144 ; 56.449,29.652 56.449,30.16 ; 56.449,29.652 56.957,29.652 ; 56.449,30.16 56.449,30.668 ; 56.449,30.16 56.957,30.16 ; 56.449,30.668 56.449,31.176 ; 56.449,30.668 56.957,30.668 ; 56.449,31.176 56.449,31.684 ; 56.449,31.176 56.957,31.176 ; 56.449,31.684 56.449,32.192 ; 56.449,31.684 56.957,31.684 ; 56.449,32.192 56.449,32.7 ; 56.449,32.192 56.957,32.192 ; 56.449,32.7 56.449,33.208 ; 56.449,32.7 56.957,32.7 ; 56.449,33.208 56.449,33.716 ; 56.449,33.208 56.957,33.208 ; 56.449,33.716 56.449,34.224 ; 56.449,33.716 56.957,33.716 ; 56.449,34.224 56.449,34.732 ; 56.449,34.224 56.957,34.224 ; 56.449,34.732 56.449,34.866 ; 56.449,34.732 56.957,34.732 ; 56.449,34.866 56.957,34.866 ; 56.449,41.938 56.449,42.352 ; 56.449,41.938 56.957,41.938 ; 56.449,42.352 56.449,42.86 ; 56.449,42.352 56.957,42.352 ; 56.449,42.86 56.449,43.368 ; 56.449,42.86 56.957,42.86 ; 56.449,43.368 56.449,43.876 ; 56.449,43.368 56.957,43.368 ; 56.449,43.876 56.449,44.384 ; 56.449,43.876 56.957,43.876 ; 56.449,44.384 56.449,44.892 ; 56.449,44.384 56.957,44.384 ; 56.449,44.892 56.449,45.4 ; 56.449,44.892 56.957,44.892 ; 56.449,45.4 56.449,45.908 ; 56.449,45.4 56.957,45.4 ; 56.449,45.908 56.449,46.416 ; 56.449,45.908 56.957,45.908 ; 56.449,46.416 56.449,46.924 ; 56.449,46.416 56.957,46.416 ; 56.449,46.924 56.449,47.432 ; 56.449,46.924 56.957,46.924 ; 56.449,47.432 56.449,47.94 ; 56.449,47.432 56.957,47.432 ; 56.449,47.94 IC4.4@56.449,48.448 ; 56.449,47.94 56.957,47.94 ; IC4.4@56.449,48.448 IC4.4@56.449,48.956 ; IC4.4@56.449,48.448 IC4.4@56.957,48.448 ; IC4.4@56.449,48.956 IC4.4@56.957,48.956 ; IC4.4@56.449,48.956 IC4.4@56.449,49.464 ; IC4.4@56.449,49.464 IC4.4@56.449,49.972 ; IC4.4@56.449,49.464 IC4.4@56.957,49.464 ; IC4.4@56.449,49.972 56.449,50.48 ; IC4.4@56.449,49.972 IC4.4@56.957,49.972 ; 56.449,50.48 56.449,50.988 ; 56.449,50.48 56.957,50.48 ; 56.449,50.988 56.449,51.496 ; 56.449,50.988 56.957,50.988 ; 56.449,51.496 56.449,52.004 ; 56.449,51.496 56.957,51.496 ; 56.449,52.004 56.449,52.512 ; 56.449,52.004 56.957,52.004 ; 56.449,52.512 56.449,53.02 ; 56.449,52.512 56.957,52.512 ; 56.449,53.02 IC4.2@56.449,53.528 ; 56.449,53.02 56.957,53.02 ; IC4.2@56.449,53.528 IC4.2@56.449,54.036 ; IC4.2@56.449,53.528 56.957,53.528 ; IC4.2@56.449,54.036 IC4.2@56.957,54.036 ; IC4.2@56.449,54.036 IC4.2@56.449,54.544 ; IC4.2@56.449,54.544 IC4.2@56.449,55.052 ; IC4.2@56.449,54.544 IC4.2@56.957,54.544 ; IC4.2@56.449,55.052 56.449,55.56 ; IC4.2@56.449,55.052 56.957,55.052 ; 56.449,55.56 56.449,56.068 ; 56.449,55.56 56.957,55.56 ; 56.449,56.068 56.449,56.08 ; 56.449,56.068 56.957,56.068 ; 56.449,56.08 56.489,56.08 56.957,56.078 ; 56.7,23.048 56.7,23.556 ; 56.7,23.048 56.957,23.048 ; 56.7,23.556 56.957,23.556 ; 56.7,23.556 56.7,24.064 ; 56.7,24.064 56.957,24.064 ; 56.7,24.064 56.7,24.572 ; 56.7,24.572 56.957,24.572 ; 56.7,24.572 56.7,25.08 ; 56.7,25.08 56.7,25.588 ; 56.7,25.08 56.957,25.08 ; 56.7,25.588 56.957,25.588 ; 56.957,20.889 56.957,21.016 ; 56.957,20.889 57.465,20.889 ; 56.957,21.016 56.957,21.524 ; 56.957,21.016 57.465,21.016 ; 56.957,21.524 56.957,22.032 ; 56.957,21.524 57.465,21.524 ; 56.957,22.032 56.957,22.54 ; 56.957,22.032 57.465,22.032 ; 56.957,22.54 56.957,23.048 ; 56.957,22.54 57.465,22.54 ; 56.957,23.048 56.957,23.556 ; 56.957,23.048 57.465,23.048 ; 56.957,23.556 56.957,24.064 ; 56.957,23.556 57.465,23.556 ; 56.957,24.064 56.957,24.572 ; 56.957,24.064 57.465,24.064 ; 56.957,24.572 56.957,25.08 ; 56.957,24.572 57.465,24.572 ; 56.957,25.08 56.957,25.588 ; 56.957,25.08 57.465,25.08 ; 56.957,25.588 56.957,26.096 ; 56.957,25.588 57.465,25.588 ; 56.957,26.096 56.957,26.604 ; 56.957,26.096 57.465,26.096 ; 56.957,26.604 56.957,27.112 ; 56.957,26.604 57.465,26.604 ; 56.957,27.112 56.957,27.62 ; 56.957,27.112 57.465,27.112 ; 56.957,27.62 56.957,28.128 ; 56.957,27.62 57.465,27.62 ; 56.957,28.128 56.957,28.636 ; 56.957,28.128 57.465,28.128 ; 56.957,28.636 56.957,29.144 ; 56.957,28.636 57.465,28.636 ; 56.957,29.144 56.957,29.652 ; 56.957,29.144 57.465,29.144 ; 56.957,29.652 56.957,30.16 ; 56.957,29.652 57.465,29.652 ; 56.957,30.16 56.957,30.668 ; 56.957,30.16 57.465,30.16 ; 56.957,30.668 56.957,31.176 ; 56.957,30.668 57.465,30.668 ; 56.957,31.176 56.957,31.684 ; 56.957,31.176 57.465,31.176 ; 56.957,31.684 56.957,32.192 ; 56.957,31.684 57.465,31.684 ; 56.957,32.192 56.957,32.7 ; 56.957,32.192 57.465,32.192 ; 56.957,32.7 56.957,33.208 ; 56.957,32.7 57.465,32.7 ; 56.957,33.208 56.957,33.716 ; 56.957,33.208 57.465,33.208 ; 56.957,33.716 56.957,34.224 ; 56.957,33.716 57.465,33.716 ; 56.957,34.224 56.957,34.732 ; 56.957,34.224 57.465,34.224 ; 56.957,34.732 56.957,34.866 ; 56.957,34.732 57.465,34.732 ; 56.957,34.866 57.465,34.866 ; 56.957,41.938 57.465,41.938 ; 56.957,41.938 56.957,42.352 ; 56.957,42.352 56.957,42.86 ; 56.957,42.352 57.465,42.352 ; 56.957,42.86 56.957,43.368 ; 56.957,42.86 57.465,42.86 ; 56.957,43.368 56.957,43.876 ; 56.957,43.368 57.465,43.368 ; 56.957,43.876 56.957,44.384 ; 56.957,43.876 57.465,43.876 ; 56.957,44.384 57.465,44.384 ; 56.957,44.384 56.957,44.892 ; 56.957,44.892 57.465,44.892 ; 56.957,44.892 56.957,45.4 ; 56.957,45.4 57.465,45.4 ; 56.957,45.4 56.957,45.908 ; 56.957,45.908 56.957,46.416 ; 56.957,45.908 57.465,45.908 ; 56.957,46.416 57.465,46.416 ; 56.957,46.416 56.957,46.924 ; 56.957,46.924 56.957,47.432 ; 56.957,46.924 57.465,46.924 ; 56.957,47.432 57.465,47.432 ; 56.957,47.432 56.957,47.94 ; 56.957,47.94 IC4.4@56.957,48.448 ; 56.957,47.94 57.465,47.94 ; IC4.4@56.957,48.448 IC4.4@56.957,48.956 ; IC4.4@56.957,48.448 IC4.4@57.465,48.448 ; IC4.4@56.957,48.956 IC4.4@57.465,48.956 ; IC4.4@56.957,48.956 IC4.4@56.957,49.464 ; IC4.4@56.957,49.464 IC4.4@56.957,49.972 ; IC4.4@56.957,49.464 IC4.4@57.465,49.464 ; IC4.4@56.957,49.972 56.957,50.48 ; IC4.4@56.957,49.972 IC4.4@57.465,49.972 ; 56.957,50.48 56.957,50.988 ; 56.957,50.48 57.465,50.48 ; 56.957,50.988 57.465,50.988 ; 56.957,50.988 56.957,51.496 ; 56.957,51.496 57.465,51.496 ; 56.957,51.496 56.957,52.004 ; 56.957,52.004 56.957,52.512 ; 56.957,52.004 57.465,52.004 ; 56.957,52.512 56.957,53.02 ; 56.957,52.512 57.465,52.512 ; 56.957,53.02 56.957,53.528 ; 56.957,53.02 57.465,53.02 ; 56.957,53.528 IC4.2@56.957,54.036 ; 56.957,53.528 57.465,53.528 ; IC4.2@56.957,54.036 IC4.2@56.957,54.544 ; IC4.2@56.957,54.036 57.448,54.036 ; IC4.2@56.957,54.544 56.957,55.052 ; IC4.2@56.957,54.544 57.448,54.544 ; 56.957,55.052 56.957,55.56 ; 56.957,55.052 57.465,55.052 ; 56.957,55.56 56.957,56.068 ; 56.957,55.56 57.465,55.56 ; 56.957,56.068 57.465,56.068 ; 56.957,56.068 56.957,56.078 ; 56.957,56.078 57.465,56.076 ; 57.448,54.036 ccw(c58.862,54.227) 57.465,53.935 ; 57.448,54.036 cw(c58.862,54.227) 57.435,54.227 57.435,54.354 cw(c58.862,54.354) 57.448,54.544 ; 57.448,54.544 cw(c58.862,54.354) 57.465,54.645 ; 57.465,20.889 57.465,21.016 ; 57.465,20.889 57.973,20.889 ; 57.465,21.016 57.465,21.524 ; 57.465,21.016 57.973,21.016 ; 57.465,21.524 57.465,22.032 ; 57.465,21.524 57.973,21.524 ; 57.465,22.032 57.465,22.54 ; 57.465,22.032 57.973,22.032 ; 57.465,22.54 57.465,23.048 ; 57.465,22.54 57.973,22.54 ; 57.465,23.048 57.465,23.556 ; 57.465,23.048 57.973,23.048 ; 57.465,23.556 57.465,24.064 ; 57.465,23.556 57.973,23.556 ; 57.465,24.064 57.465,24.572 ; 57.465,24.064 57.973,24.064 ; 57.465,24.572 57.465,25.08 ; 57.465,24.572 57.973,24.572 ; 57.465,25.08 57.465,25.588 ; 57.465,25.08 57.973,25.08 ; 57.465,25.588 57.465,26.096 ; 57.465,25.588 57.973,25.588 ; 57.465,26.096 57.465,26.604 ; 57.465,26.096 57.973,26.096 ; 57.465,26.604 57.465,27.112 ; 57.465,26.604 57.973,26.604 ; 57.465,27.112 57.465,27.62 ; 57.465,27.112 57.973,27.112 ; 57.465,27.62 57.465,28.128 ; 57.465,27.62 57.973,27.62 ; 57.465,28.128 57.465,28.636 ; 57.465,28.128 57.973,28.128 ; 57.465,28.636 57.465,29.144 ; 57.465,28.636 57.973,28.636 ; 57.465,29.144 57.465,29.652 ; 57.465,29.144 57.973,29.144 ; 57.465,29.652 57.465,30.16 ; 57.465,29.652 57.973,29.652 ; 57.465,30.16 57.465,30.668 ; 57.465,30.16 57.973,30.16 ; 57.465,30.668 57.465,31.176 ; 57.465,30.668 57.973,30.668 ; 57.465,31.176 57.465,31.684 ; 57.465,31.176 57.973,31.176 ; 57.465,31.684 57.465,32.192 ; 57.465,31.684 57.973,31.684 ; 57.465,32.192 57.465,32.7 ; 57.465,32.192 57.973,32.192 ; 57.465,32.7 57.465,33.208 ; 57.465,32.7 57.973,32.7 ; 57.465,33.208 57.465,33.716 ; 57.465,33.208 57.973,33.208 ; 57.465,33.716 57.465,34.224 ; 57.465,33.716 57.973,33.716 ; 57.465,34.224 57.465,34.732 ; 57.465,34.224 57.973,34.224 ; 57.465,34.732 57.465,34.866 ; 57.465,34.732 57.973,34.732 ; 57.465,34.866 57.973,34.866 ; 57.465,41.938 57.465,42.352 ; 57.465,42.352 57.465,42.86 ; 57.465,42.352 57.786,42.352 ; 57.465,42.86 57.465,43.368 ; 57.465,42.86 57.973,42.86 ; 57.465,43.368 57.465,43.876 ; 57.465,43.368 57.973,43.368 ; 57.465,43.876 57.465,44.384 ; 57.465,43.876 57.973,43.876 ; 57.465,44.384 57.465,44.892 ; 57.465,44.384 57.973,44.384 ; 57.465,44.892 57.973,44.892 ; 57.465,44.892 57.465,45.4 ; 57.465,45.4 57.465,45.908 ; 57.465,45.4 57.973,45.4 ; 57.465,45.908 57.465,46.416 ; 57.465,45.908 57.973,45.908 ; 57.465,46.416 57.973,46.416 ; 57.465,46.416 57.465,46.924 ; 57.465,46.924 57.465,47.432 ; 57.465,46.924 57.973,46.924 ; 57.465,47.432 57.973,47.432 ; 57.465,47.432 57.465,47.94 ; 57.465,47.94 IC4.4@57.465,48.448 ; 57.465,47.94 57.973,47.94 ; IC4.4@57.465,48.448 IC4.4@57.465,48.956 ; IC4.4@57.465,48.448 57.973,48.448 ; IC4.4@57.465,48.956 57.973,48.956 ; IC4.4@57.465,48.956 IC4.4@57.465,49.464 ; IC4.4@57.465,49.464 IC4.4@57.465,49.972 ; IC4.4@57.465,49.464 57.973,49.464 ; IC4.4@57.465,49.972 57.465,50.48 ; IC4.4@57.465,49.972 57.973,49.972 ; 57.465,50.48 57.465,50.988 ; 57.465,50.48 57.973,50.48 ; 57.465,50.988 57.973,50.988 ; 57.465,50.988 57.465,51.496 ; 57.465,51.496 57.973,51.496 ; 57.465,51.496 57.465,52.004 ; 57.465,52.004 57.465,52.512 ; 57.465,52.004 57.973,52.004 ; 57.465,52.512 57.465,53.02 ; 57.465,52.512 57.973,52.512 ; 57.465,53.02 57.973,53.02 ; 57.465,53.02 57.465,53.528 ; 57.465,53.528 57.465,53.935 ; 57.465,53.528 57.618,53.528 ; 57.465,53.935 ccw(c58.862,54.227) 57.614,53.535 ccw(c58.862,54.227) 57.618,53.528 ; 57.465,54.645 cw(c58.862,54.354) 57.614,55.045 cw(c58.862,54.354) 57.618,55.052 ; 57.465,54.645 57.465,55.052 ; 57.465,55.052 57.465,55.56 ; 57.465,55.052 57.618,55.052 ; 57.465,55.56 57.465,56.068 ; 57.465,55.56 57.973,55.56 ; 57.465,56.068 57.973,56.068 ; 57.465,56.068 57.465,56.076 ; 57.465,56.076 57.973,56.075 ; 57.618,53.528 ccw(c58.862,54.227) 57.964,53.117 ccw(c58.862,54.227) 57.973,53.11 ; 57.786,42.352 cw(c58.656,41.895) 57.789,42.356 cw(c58.656,41.895) 57.973,42.601 57.973,42.86 ; 57.973,20.889 57.973,21.016 ; 57.973,20.889 58.481,20.889 ; 57.973,21.016 57.973,21.524 ; 57.973,21.016 58.481,21.016 ; 57.973,21.524 57.973,22.032 ; 57.973,21.524 58.481,21.524 ; 57.973,22.032 57.973,22.54 ; 57.973,22.032 58.481,22.032 ; 57.973,22.54 57.973,23.048 ; 57.973,22.54 58.481,22.54 ; 57.973,23.048 57.973,23.556 ; 57.973,23.048 58.481,23.048 ; 57.973,23.556 57.973,24.064 ; 57.973,23.556 58.481,23.556 ; 57.973,24.064 57.973,24.572 ; 57.973,24.064 58.481,24.064 ; 57.973,24.572 57.973,25.08 ; 57.973,24.572 58.481,24.572 ; 57.973,25.08 57.973,25.588 ; 57.973,25.08 58.481,25.08 ; 57.973,25.588 57.973,26.096 ; 57.973,25.588 58.481,25.588 ; 57.973,26.096 57.973,26.604 ; 57.973,26.096 58.481,26.096 ; 57.973,26.604 57.973,27.112 ; 57.973,26.604 58.481,26.604 ; 57.973,27.112 57.973,27.62 ; 57.973,27.112 58.481,27.112 ; 57.973,27.62 57.973,28.128 ; 57.973,27.62 58.481,27.62 ; 57.973,28.128 57.973,28.636 ; 57.973,28.128 58.481,28.128 ; 57.973,28.636 57.973,29.144 ; 57.973,28.636 58.481,28.636 ; 57.973,29.144 57.973,29.652 ; 57.973,29.144 58.481,29.144 ; 57.973,29.652 57.973,30.16 ; 57.973,29.652 58.481,29.652 ; 57.973,30.16 57.973,30.668 ; 57.973,30.16 58.481,30.16 ; 57.973,30.668 57.973,31.176 ; 57.973,30.668 58.481,30.668 ; 57.973,31.176 57.973,31.684 ; 57.973,31.176 58.481,31.176 ; 57.973,31.684 57.973,32.192 ; 57.973,31.684 58.481,31.684 ; 57.973,32.192 57.973,32.7 ; 57.973,32.192 58.481,32.192 ; 57.973,32.7 57.973,33.208 ; 57.973,32.7 58.481,32.7 ; 57.973,33.208 57.973,33.716 ; 57.973,33.208 58.481,33.208 ; 57.973,33.716 57.973,34.224 ; 57.973,33.716 58.481,33.716 ; 57.973,34.224 pad.@58.481,34.224 ; 57.973,34.224 57.973,34.732 ; 57.973,34.732 57.973,34.866 ; 57.973,34.732 pad.@58.481,34.732 ; 57.973,34.866 58.481,34.866 ; 57.973,42.86 57.973,43.368 ; 57.973,42.86 58.471,42.86 ; 57.973,43.368 57.973,43.876 ; 57.973,43.368 58.481,43.368 ; 57.973,43.876 57.973,44.384 ; 57.973,43.876 58.481,43.876 ; 57.973,44.384 57.973,44.892 ; 57.973,44.384 58.481,44.384 ; 57.973,44.892 57.973,45.4 ; 57.973,44.892 58.481,44.892 ; 57.973,45.4 57.973,45.908 ; 57.973,45.4 58.481,45.4 ; 57.973,45.908 57.973,46.416 ; 57.973,45.908 58.481,45.908 ; 57.973,46.416 57.973,46.924 ; 57.973,46.416 58.481,46.416 ; 57.973,46.924 57.973,47.432 ; 57.973,46.924 58.481,46.924 ; 57.973,47.432 57.973,47.94 ; 57.973,47.432 58.481,47.432 ; 57.973,47.94 57.973,48.448 ; 57.973,47.94 58.481,47.94 ; 57.973,48.448 57.973,48.956 ; 57.973,48.448 58.481,48.448 ; 57.973,48.956 57.973,49.464 ; 57.973,48.956 58.481,48.956 ; 57.973,49.464 57.973,49.972 ; 57.973,49.464 58.481,49.464 ; 57.973,49.972 57.973,50.48 ; 57.973,49.972 58.481,49.972 ; 57.973,50.48 57.973,50.988 ; 57.973,50.48 58.481,50.48 ; 57.973,50.988 57.973,51.496 ; 57.973,50.988 58.481,50.988 ; 57.973,51.496 57.973,52.004 ; 57.973,51.496 58.481,51.496 ; 57.973,52.004 57.973,52.512 ; 57.973,52.004 58.481,52.004 ; 57.973,52.512 57.973,53.02 ; 57.973,52.512 58.481,52.512 ; 57.973,53.02 58.1,53.02 ; 57.973,53.02 57.973,53.11 ; 57.973,53.11 ccw(c58.862,54.227) 58.1,53.02 ; 57.973,55.56 57.973,56.068 ; 57.973,55.56 58.1,55.56 ; 57.973,56.068 57.973,56.075 ; 57.973,56.068 58.481,56.068 ; 57.973,56.075 58.481,56.073 ; 58.1,55.56 cw(c58.862,54.354) 58.481,55.729 ; 58.471,42.86 cw(c58.656,41.895) 58.481,42.862 ; 58.481,20.889 58.481,21.016 ; 58.481,20.889 58.989,20.889 ; 58.481,21.016 58.481,21.524 ; 58.481,21.016 58.989,21.016 ; 58.481,21.524 58.481,22.032 ; 58.481,21.524 58.989,21.524 ; 58.481,22.032 58.481,22.54 ; 58.481,22.032 58.989,22.032 ; 58.481,22.54 58.481,23.048 ; 58.481,22.54 58.989,22.54 ; 58.481,23.048 58.481,23.556 ; 58.481,23.048 58.989,23.048 ; 58.481,23.556 58.481,24.064 ; 58.481,23.556 58.989,23.556 ; 58.481,24.064 58.481,24.572 ; 58.481,24.064 58.989,24.064 ; 58.481,24.572 58.481,25.08 ; 58.481,24.572 58.989,24.572 ; 58.481,25.08 58.481,25.588 ; 58.481,25.08 58.989,25.08 ; 58.481,25.588 58.481,26.096 ; 58.481,25.588 58.989,25.588 ; 58.481,26.096 58.481,26.604 ; 58.481,26.096 58.989,26.096 ; 58.481,26.604 58.481,27.112 ; 58.481,26.604 58.989,26.604 ; 58.481,27.112 58.481,27.62 ; 58.481,27.112 58.989,27.112 ; 58.481,27.62 58.481,28.128 ; 58.481,27.62 58.989,27.62 ; 58.481,28.128 58.481,28.636 ; 58.481,28.128 58.989,28.128 ; 58.481,28.636 58.481,29.144 ; 58.481,28.636 58.989,28.636 ; 58.481,29.144 58.481,29.652 ; 58.481,29.144 58.989,29.144 ; 58.481,29.652 58.481,30.16 ; 58.481,29.652 58.989,29.652 ; 58.481,30.16 58.481,30.668 ; 58.481,30.16 58.989,30.16 ; 58.481,30.668 58.481,31.176 ; 58.481,30.668 58.989,30.668 ; 58.481,31.176 58.481,31.684 ; 58.481,31.176 58.989,31.176 ; 58.481,31.684 58.481,32.192 ; 58.481,31.684 58.989,31.684 ; 58.481,32.192 58.481,32.7 ; 58.481,32.192 58.989,32.192 ; 58.481,32.7 58.481,33.208 ; 58.481,32.7 58.989,32.7 ; 58.481,33.208 58.481,33.716 ; 58.481,33.208 58.989,33.208 ; 58.481,33.716 pad.@58.481,34.224 ; 58.481,33.716 58.989,33.716 ; pad.@58.481,34.224 58.989,34.224 ; pad.@58.481,34.224 pad.@58.481,34.732 ; pad.@58.481,34.732 58.481,34.866 ; pad.@58.481,34.732 58.989,34.732 ; 58.481,34.866 58.989,34.866 ; 58.481,42.862 58.481,43.368 ; 58.481,43.368 58.989,43.368 ; 58.481,43.368 58.481,43.876 ; 58.481,43.876 58.481,44.384 ; 58.481,43.876 58.989,43.876 ; 58.481,44.384 58.481,44.892 ; 58.481,44.384 58.989,44.384 ; 58.481,44.892 58.481,45.4 ; 58.481,44.892 58.989,44.892 ; 58.481,45.4 58.481,45.908 ; 58.481,45.4 58.989,45.4 ; 58.481,45.908 58.481,46.416 ; 58.481,45.908 58.989,45.908 ; 58.481,46.416 58.481,46.924 ; 58.481,46.416 58.989,46.416 ; 58.481,46.924 58.481,47.432 ; 58.481,46.924 58.989,46.924 ; 58.481,47.432 58.481,47.94 ; 58.481,47.432 58.989,47.432 ; 58.481,47.94 58.481,48.448 ; 58.481,47.94 58.989,47.94 ; 58.481,48.448 58.481,48.956 ; 58.481,48.448 58.989,48.448 ; 58.481,48.956 58.481,49.464 ; 58.481,48.956 58.989,48.956 ; 58.481,49.464 58.481,49.972 ; 58.481,49.464 58.989,49.464 ; 58.481,49.972 58.481,50.48 ; 58.481,49.972 58.989,49.972 ; 58.481,50.48 58.481,50.988 ; 58.481,50.48 58.989,50.48 ; 58.481,50.988 58.481,51.496 ; 58.481,50.988 58.989,50.988 ; 58.481,51.496 58.481,52.004 ; 58.481,51.496 58.989,51.496 ; 58.481,52.004 58.481,52.512 ; 58.481,52.004 58.989,52.004 ; 58.481,52.512 58.989,52.512 ; 58.481,55.729 cw(c58.862,54.354) 58.493,55.732 cw(c58.862,54.354) 58.862,55.781 cw(c58.862,54.354) 58.989,55.775 ; 58.481,55.729 58.481,56.068 ; 58.481,56.068 58.481,56.073 ; 58.481,56.068 58.989,56.068 ; 58.481,56.073 58.989,56.071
